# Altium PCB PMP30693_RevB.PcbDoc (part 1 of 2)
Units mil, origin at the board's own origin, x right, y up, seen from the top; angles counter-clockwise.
Board outline 2800 x 2253.94 mil, 2 copper layers (Top Layer, Bottom Layer), stack 62 mil thick; 97 components, 41 nets, 215 pads, 48 vias.
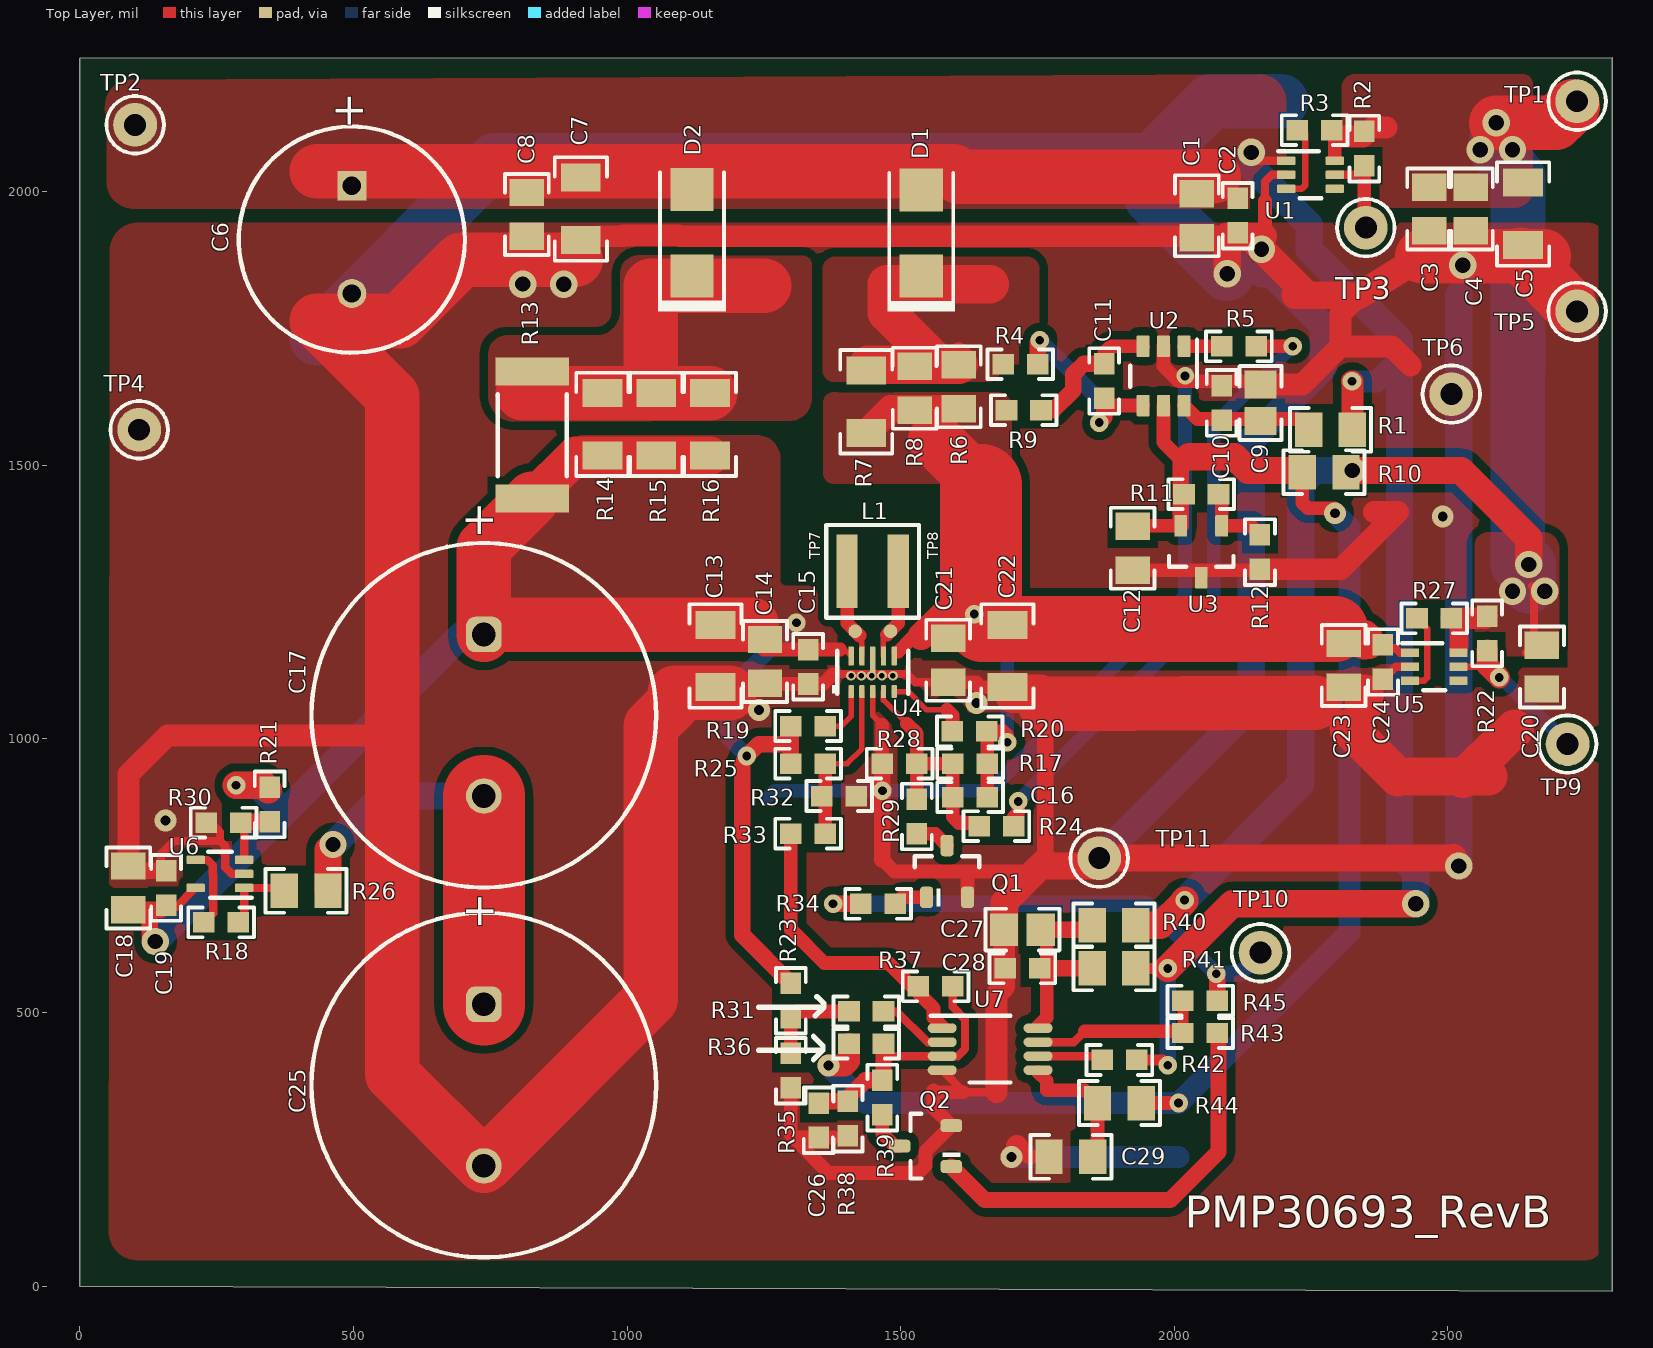
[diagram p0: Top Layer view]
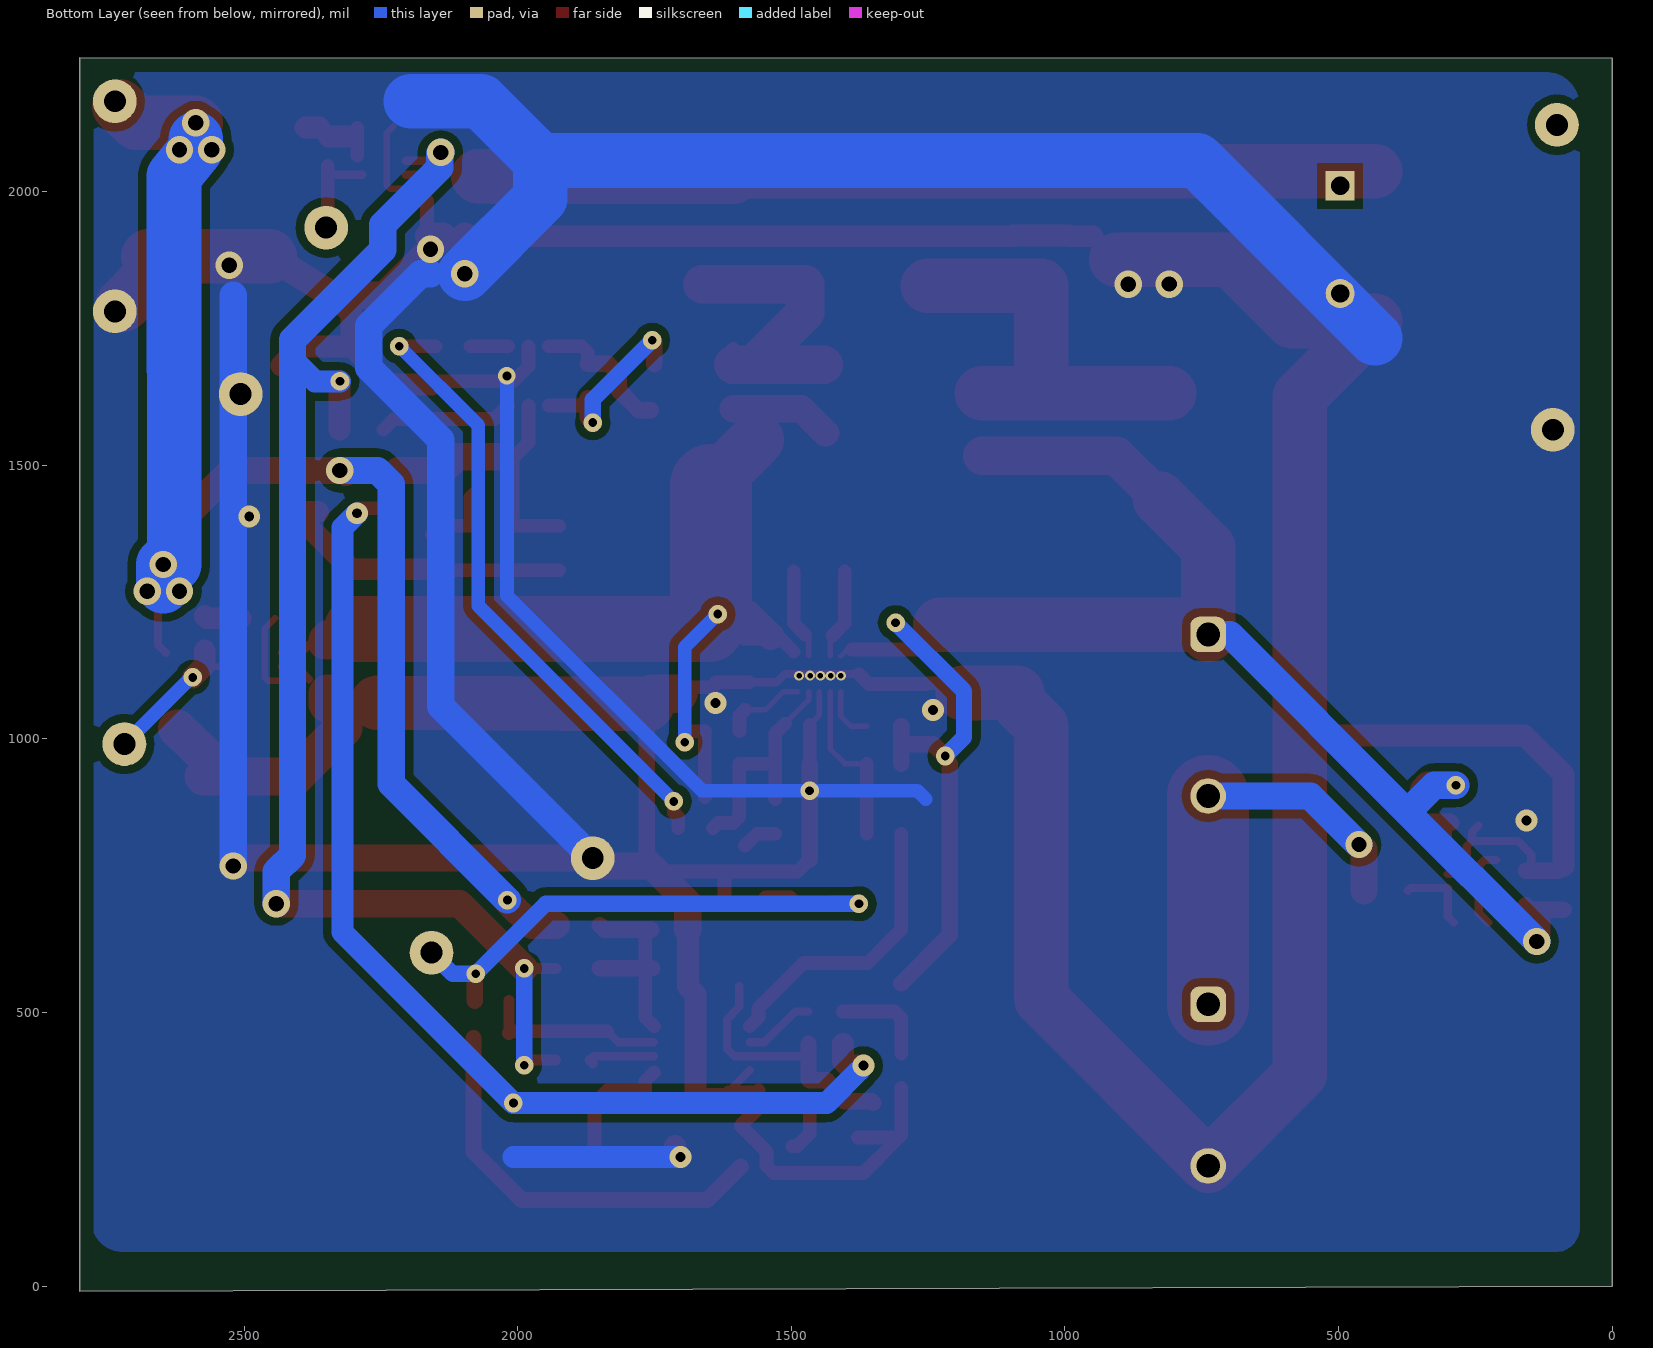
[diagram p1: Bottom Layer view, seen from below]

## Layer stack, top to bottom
Top Solder: solder mask 0.4, Solder Resist, Dk 3.5
Top Layer: signal copper 1.4
Dielectric1: core 59.2, FR-4, Dk 4.8
Bottom Layer: signal copper 1.4
Bottom Solder: solder mask 0.4, Solder Resist, Dk 3.5

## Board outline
0,0 0,2244.09 2800,2244.56 2800,-9.38

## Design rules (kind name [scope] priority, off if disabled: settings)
AcuteAngle [All] p1: minimum=4.50000000000000E+0001 checktracksonly=FALSE
AssemblyTestPointUsage [All] p1: valid=2
BoardOutlineClearance BoardOutlineClearance_MountingHoles [OnCopper and InComponentClass('Mounting Holes')] p1: gap=39.37 ignorepadtopadclearanceinfootprint=FALSE
BoardOutlineClearance BoardOutlineClearance_Poly [OnCopper and IsPoly] p2: gap=25 ignorepadtopadclearanceinfootprint=FALSE
BoardOutlineClearance [OnCopper and Not InComponentClass('Logo') and not InComponentClass('FiducialMark') and not InRegion(1000,500,4000,800) and not InPoly] p3: gap=15 ignorepadtopadclearanceinfootprint=FALSE
Clearance Clearance_Keepouts [((IsTrack Or IsArc) And Not InPoly) And IsFree and IsKeepOut vs ((IsTrack Or IsArc) And Not InPoly) And IsFree and IsKeepOut] p1: gap=0 ignorepadtopadclearanceinfootprint=FALSE
Clearance Clearance_Poly [InPolygon] p2: gap=15 ignorepadtopadclearanceinfootprint=TRUE
Clearance Clearance_FiducialMark [IsKeepOut and InComponentClass('FiducialMark') vs IsPad and InComponentClass('FiducialMark')] p3: gap=0 ignorepadtopadclearanceinfootprint=FALSE
Clearance [All] p4: gap=7.87 ignorepadtopadclearanceinfootprint=TRUE
ComponentClearance ComponentClearance_MountingHoles_FiducialMarks [InComponentClass('Mounting Holes') vs InComponentClass('FiducialMark')] p1: gap=50 collisioncheckmode=3 verticalgap=10 showdistances=FALSE
ComponentClearance ComponentClearance_Shunt [InComponentClass('Header') vs InComponentClass('Shunt')] p2: gap=0 collisioncheckmode=3 verticalgap=0 showdistances=FALSE
ComponentClearance ComponentClearance_Logo [InComponentClass('Logo')] p3: gap=50 collisioncheckmode=3 verticalgap=10 showdistances=FALSE
ComponentClearance ComponentClearance_ScrewToNut [(HasFootprint('NY PMS 440 0025 PH')) vs (HasFootprint('Keystone_1902C'))] p4: gap=5 collisioncheckmode=3 verticalgap=10 showdistances=FALSE
ComponentClearance ComponentClearance_MountingHoles [InComponentClass('Mounting Holes')] p5: gap=250 collisioncheckmode=3 verticalgap=100000 showdistances=FALSE
ComponentClearance ComponentClearance_SmallPassives [HasFootprint('0201*') or HasFootprint('0402*') or HasFootprint('0508') or HasFootprint('0603*') or HasFootprint('0612') or HasFootprint('0805*') or HasFootprint('0815*') or HasFootprint('0830*') or HasFootprint('1206*') or HasFootprint('1210*') or HasFootprint('1808*') or HasFootprint('1812*') or HasFootprint('1825*') or HasFootprint('2010*') or HasFootprint('2220*') or HasFootprint('2225*') or HasFootprint('2512*') or HasFootprint('2728*') or HasFootprint('3518*') vs HasFootprint('0201*') or HasFootprint('0402*') or HasFootprint('0508') or HasFootprint('0603*') or HasFootprint('0612') or HasFootprint('0805*') or HasFootprint('0815*') or HasFootprint('0830*') or HasFootprint('1206*') or HasFootprint('1210*') or HasFootprint('1808*') or HasFootprint('1812*') or HasFootprint('1825*') or HasFootprint('2010*') or HasFootprint('2220*') or HasFootprint('2225*') or HasFootprint('2512*') or HasFootprint('2728*') or HasFootprint('3518*')] p6: gap=14.96 collisioncheckmode=3 verticalgap=10 showdistances=FALSE
ComponentClearance ComponentClearance_THtoSMT [IsThruComponent vs IsSMTComponent] p7: gap=20 collisioncheckmode=3 verticalgap=20 showdistances=FALSE
ComponentClearance ComponentClearance_THtoTH [IsThruComponent vs IsThruComponent] p8: gap=30 collisioncheckmode=3 verticalgap=30 showdistances=FALSE
ComponentClearance [All] p9: gap=6 collisioncheckmode=3 verticalgap=6 showdistances=FALSE
DiffPairsRouting [All] p1: maxlimit=100 minlimit=10 mostfreqgap=10 toplayer_minwidth=15 toplayer_maxwidth=15 toplayer_prefwidth=15 bottomlayer_minwidth=15 bottomlayer_maxwidth=15 bottomlayer_prefwidth=15 maxuncoupledlength=1000
FabricationTestPointUsage TestPointUsage [All] p1: valid=2 allowmultiple=FALSE
FabricationTestpoint Testpoint [All] p1: side=3 testpointundercomponent=TRUE minsize=40 maxsize=100 preferedsize=60 minholesize=0 maxholesize=40 preferedholesize=32 testpointgrid=1 allowsidetop=TRUE allowsidebottom=TRUE usegrid=TRUE gridtolerance=0.01
FanoutControl Fanout_LCC [IsLCC] p1: bgadir=Out bgaviamode=Centered fanoutstyle=Auto fanoutdirection=Alternating viagrid=1 // Fanout_LCC (Default Rule)
FanoutControl Fanout_BGA [IsBGA] p2: bgadir=Out bgaviamode=Centered fanoutstyle=Auto fanoutdirection=Alternating viagrid=1 // Fanout_BGA (Default Rule)
FanoutControl Fanout_Default [All] p4: bgadir=Out bgaviamode=Centered fanoutstyle=Auto fanoutdirection=Alternating viagrid=1 // Fanout_Default (Default Rule)
FanoutControl Fanout_Small [(CompPinCount < 5)] p5: bgadir=Out bgaviamode=Centered fanoutstyle=Auto fanoutdirection=OutThenIn viagrid=1 // Fanout_Small (Default Rule)
Height [All] p1: minheight=0 maxheight=3000 prefheight=500
HoleSize [All] p1: absolutevalues=TRUE maxlimit=251 minlimit=7.87 maxpercent=80.000 minpercent=20.000
HoleToHoleClearance [All] p1: gap=7 allowstackedmicrovias=TRUE
MinimumAnnularRing MinimumAnnularRing_ThermalPadVias [IsVia and InAnyComponent] p1: minimumring=5.91
MinimumAnnularRing [All] p2: minimumring=4
MinimumSolderMaskSliver MinimumSolderMaskSliver_Logo [InComponentClass('Logo') vs InComponentClass('Logo')] p1: minsoldermaskwidth=0.7
MinimumSolderMaskSliver [All] p2: minsoldermaskwidth=1
PlaneConnect [All] p1: planeconnectstyle=Relief reliefexpansion=10 reliefentries=4 reliefconductorwidth=10 reliefairgap=10
PolygonConnect [All] p1: connectstyle=Direct reliefconductorwidth=10 reliefentries=4 polygonreliefangle="90 Angle" airgapwidth=10
RoutingVias ThermalPadVias [IsVia and InAnyComponent] p1: holewidth=7.87 width=19.68 viastyle="Through Hole" minholewidth=7.87 minwidth=19.68 maxholewidth=12.99 maxwidth=23.62
RoutingVias [All] p2: holewidth=16 width=34 viastyle="Through Hole" minholewidth=6 minwidth=15 maxholewidth=40 maxwidth=65
SilkToBoardRegionClearance [Not ((IsComment or IsDesignator) And (Hide <> 'False')) and not InRegion(1000,500,4000,800)] p1:
SilkToSilkClearance SilkToSilkClearance_Pb-FreeLogo [(HasFootprint('Pb-Free_Overlay_Medium') OR HasFootprint('Pb-Free_Overlay_Small')) vs (HasFootprint('Pb-Free_Overlay_Medium') OR HasFootprint('Pb-Free_Overlay_Small'))] p1 off: silktosilkclearance=0
SilkToSilkClearance [All] p2 off: silktosilkclearance=3.94
SilkToSolderMaskClearance SilkToComponentPadClearance [(IsPad or IsFill or IsRegion) and InAnycomponent] p1 off: minsilkscreentomaskgap=5 clearancetoexposedcopper=TRUE
SilkToSolderMaskClearance "Silk to Solder Mask Opening" [All] p2 off: minsilkscreentomaskgap=3.94 clearancetoexposedcopper=FALSE
SolderMaskExpansion [All] p1: expansion=1.97
UnRoutedNet [All] p1: checkbadconnections=TRUE
Width [All] p1: maxlimit=200 minlimit=6 preferedwidth=10 checkconnectedcopper=TRUE
12 further rules are at their usual default settings.

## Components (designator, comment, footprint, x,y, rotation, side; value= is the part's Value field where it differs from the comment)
C1 "GRM21BR71A105KA01L" 0805_HV 2041.14,1956.25 r270 top value=1uF
C2 "GRM188R71H104KA93D" 0603 2115.62,1956.25 r270 top value=0.1uF
C3 "GRM21BR71A105KA01L" 0805_HV 2465.62,1968.5 r270 top value=1uF
C4 "GRM21BR70J106KE76L" 0805_HV 2541.86,1968.5 r270 top value=10uF
C5 "DNP" 1206 2637.5,1959.38 r270 top
C6 "EKZM160ELL102MJ20S" Chemi-Con_1000x2000 496.88,1912.5 r270 top value=1000uF
C7 "DNP" 1206 915.35,1968.5 r270 top
C8 "GRM21BR70J106KE76L" 0805_HV 816.93,1958.66 r270 top value=10uF
C9 "DNP" 0805 2157.48,1614.17 r90 top
C10 "GRM188R71H104KA93D" 0603 2086.61,1614.17 r90 top value=0.1uF
C11 "C0603C334K4RACTU" 0603 1871.88,1654.13 r270 top value=0.33uF
C12 "C0805C155K8RACTU" 0805_HV 1923.86,1348.43 r270 top value=1.5uF
C13 "DNP" 1206 1161.42,1151.57 r270 top
C14 "GRM21BR70J106KE76L" 0805_HV 1251.97,1141.73 r270 top value=10uF
C15 "GRM188R71H104KA93D" 0603 1330.71,1131.89 r270 top value=0.1uF
C16 "Used in BOM report" 0603 1626.7,893.7 r180 top value=DNP
C17 "SCCU25B256SRB" SCC_1600x2650 738.19,1043.31 r270 top value=25000000uF
C18 "GRM21BR71A105KA01L" 0805_HV 88.58,727.72 r90 top value=1uF
C19 "GRM188R71H104KA93D" 0603 157.48,727.72 r90 top value=0.1uF
C20 "GRM21BR71A105KA01L" 0805_HV 2671.88,1131.25 r270 top value=1uF
C21 "CL21B226MQQNNNE" 0805_HV 1586.61,1143.7 r270 top value=22uF
C22 "Used in BOM report" 1206 1694.88,1151.57 r270 top value=DNP
C23 "GRM21BR71A105KA01L" 0805_HV 2309.38,1134.38 r270 top value=1uF
C24 "GRM188R71H104KA93D" 0603 2381.25,1140.62 r270 top value=0.1uF
C25 "SCCU25B256SRB" SCC_1600x2650 738.19,367.42 r270 top value=25000000uF
C26 "DNP" 0603 1350,303.12 r270 top
C27 "Used in BOM report" 0805 1722.44,651.57 r180 top value=DNP
C28 "GRM188R71H104KA93D" 0603 1722.44,580.71 r180 top value=0.1uF
C29 "C0805C105K8RACTU" 0805_HV 1811.02,236.22 r180 top value=1uF
D1 "MBRA210LT3G" SMA 1537.5,1924.75 r90 top value=10V
D2 "MBRA210LT3G" SMA 1118.75,1925 r90 top value=10V
L1 "XFL4015-471MEC" XFL4015 1448.82,1306.25 r0 top value=470nH
Q1 "MMBT2222A" SOT-23 1584.65,757.87 r90 top value="40 V"
Q2 "MMBT2222A" SOT-23 1545.28,255.91 r180 top value="40 V"
R1 "CRCW08050000Z0EA" 0805_HV 2285.43,1564.96 r0 top value=0
R2 "CRCW06030000Z0EA" 0603 2347.25,2078.81 r90 top value=0
R3 "CRCW06030000Z0EA" 0603 2256.25,2112.5 r180 top value=0
R4 "CRCW0603499RFKEA" 0603 1718.56,1684.72 r0 top value=499
R5 "CRCW06030000Z0EA" 0603 2118.11,1717.52 r180 top value=0
R6 "Used in BOM report" 0805_HV 1606.3,1643.7 r90 top value=DNP
R7 "ERJ-8BWFR068V" 1206 1437.01,1616.14 r90 top value=0.068
R8 "Used in BOM report" 0805_HV 1525.59,1641 r90 top value=DNP
R9 "CRCW0603499RFKEA" 0603 1724.84,1600.82 r0 top value=499
R10 "CRCW08052K00FKEA" 0805_HV 2273.62,1487.5 r180 top value=2.00k
R11 "CRCW0603100RFKEA" 0603 2049.21,1447.3 r180 top value=100
R12 "CRCW060312K4FKEA" 0603 2156.5,1341.54 r90 top value=12.4k
R13 "Used in BOM report" 2512 826.77,1555.12 r90 top value=DNP
R14 "CRCW120630R1FKEA" 1206 954.72,1574.8 r90 top value=30.1
R15 "CRCW120630R1FKEA" 1206 1053.15,1574.8 r90 top value=30.1
R16 "CRCW120630R1FKEA" 1206 1151.57,1574.8 r90 top value=30.1
R17 "CRCW0603392KFKEA" 0603 1626.7,954.72 r0 top value=392k
R18 "CRCW06030000Z0EA" 0603 257.87,664.72 r0 top value=0
R19 "CRCW06030000Z0EA" 0603 1330.71,1023.62 r0 top value=0
R20 "CRCW0603100KFKEA" 0603 1625.98,1013.78 r0 top value=100k
R21 "CRCW06031M00FKEA" 0603 346.88,880.3 r90 top value=1.00Meg
R22 "CRCW06030000Z0EA" 0603 2571.88,1192.91 r90 top value=0
R23 "CRCW0603301KFKEA" 0603 1299.21,521.65 r90 top value=301k
R24 "CRCW0603100KFKEA" 0603 1675,840.62 r0 top value=100k
R25 "DNP" 0603 1330.71,954.72 r0 top
R26 "CRCW08051K00FKEA" 0805_HV 413.39,722.44 r0 top value=1.00k
R27 "CRCW06030000Z0EA" 0603 2475,1220.47 r180 top value=0
R28 "CRCW060382K5FKEA" 0603 1498.03,954.72 r0 top value=82.5k
R29 "CRCW0603187KFKEA" 0603 1529.53,858.27 r90 top value=187k
R30 "CRCW06031M00FKEA" 0603 262.5,846.88 r0 top value=1.00Meg
R31 "CRCW06030000Z0EA" 0603 1437.01,501.97 r0 top value=0
R32 "DNP" 0603 1387.5,895.67 r0 top
R33 "CRCW060310K0FKEA" 0603 1330.71,826.77 r0 top value=10.0k
R34 "CRCW0603100KFKEA" 0603 1458.66,698.82 r180 top value=100k
R35 "CRCW060343K2FKEA" 0603 1299.21,393.7 r90 top value=43.2k
R36 "CRCW0603100KFKEA" 0603 1437.01,442.91 r0 top value=100k
R37 "CRCW06033M01FKEA" 0603 1563.78,548.06 r180 top value=3.01Meg
R38 "CRCW060390K9FKEA" 0603 1403.12,306.25 r90 top value=90.9k
R39 "CRCW06030000Z0EA" 0603 1466.54,344.49 r270 top value=0
R40 "CRCW08050000Z0EA" 0805_HV 1889.76,659.45 r180 top value=0
R41 "DNP" 0805_HV 1889.76,580.71 r180 top
R42 "CRCW060310K0FKEA" 0603 1899.61,413.39 r180 top value=10.0k
R43 "CRCW0603100KFKEA" 0603 2047.24,462.6 r0 top value=100k
R44 "CRCW0805100RJNEA" 0805_HV 1899.61,334.65 r180 top value=100
R45 "CRCW06030000Z0EA" 0603 2047.24,521.65 r0 top value=0
TP1 "5000" Keystone5000 2736.22,2165.35 r90 top
TP2 "5000" Keystone5000 100.88,2122.33 r90 top
TP3 "5000" Keystone5000 2350,1934.38 r90 top
TP4 "5001" Keystone5001 108.27,1564.96 r90 top
TP5 "5001" Keystone5001 2736.22,1781.5 r90 top
TP6 "5001" Keystone5001 2506.25,1630.14 r90 top
TP7 "TP-025-SMT" TP_25MIL-SMT 1416.82,1196.88 r90 top value=STD
TP8 "TP-025-SMT" TP_25MIL-SMT 1481.17,1196.97 r90 top value=STD
TP9 "5000" Keystone5000 2718.75,990.62 r90 top
TP10 "5000" Keystone5000 2157.48,609.38 r90 top
TP11 "5001" Keystone5001 1862.8,782.09 r90 top
U1 "LM66100DCKT" DCK0006A_N 2248.83,2031.23 r0 top
U2 "INA181A4IDBV" DBV0006A_N 1980.31,1663.39 r270 top
U3 "TLV431AIDBZR" DBZ0003A_N 2049.21,1342.16 r270 top
U4 "TPS63802DLAR" DLA0010A 1448.82,1122.05 r90 top
U5 "LM66100DCKT" DCK0006A_N 2475,1131.89 r0 top
U6 "TLV521DCKR" DCK0005A_N 255.91,753.31 r180 top
U7 "TLV522DGKR" DGK0008A_N 1663.39,433.07 r0 top

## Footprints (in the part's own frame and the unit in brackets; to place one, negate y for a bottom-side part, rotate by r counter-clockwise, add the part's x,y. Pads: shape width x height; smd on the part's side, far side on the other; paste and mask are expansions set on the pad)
0603 [mm] "0603 from SM-752 data"
  rect 1x0.95 smd: 1(-0.8,0) 2(0.8,0)
  silkscreen extent -1.52,-0.69 1.52,0.69, body extent -0.87,-0.47 0.87,0.47, height 1
0805 [mm] "0805 from SM-752 data"
  rect 1.3x1.5 smd: 1(-0.85,0) 2(0.85,0)
  silkscreen extent -1.72,-0.97 1.72,0.97, body extent -1.1,-0.72 1.1,0.72, height 1.45
0805_HV [mil] "0805 with 30mil clearance between pads"
  rect 50x63 smd: 1(-40,0) 2(40,0)
  silkscreen extent -74,-40 74,40, body extent -43,-29 43,29, height 57
1206 [mm] "1206 from SM-752 data"
  rect 1.3x1.85 smd: 1(-1.45,0) 2(1.45,0)
  silkscreen extent -2.4,-1.21 2.4,1.21, body extent -1.7,-0.9 1.7,0.9, height 1.35
2512 [mm] "Chip Resistor, Body 6.3x3.2mm, IPC Medium Density"
  rect 1.3x3.4 smd: 1(-2.95,0) 2(2.95,0)
  silkscreen extent -1.9,-1.6 1.9,1.6, body extent -3.22,-1.67 3.22,1.67, height 0.71
Chemi-Con_1000x2000 [mm] "TH, 2-Leads, Body 10x20mm, Pin Spacing 5mm"
  rect 1.35x1.35 hole 0.85: 1(-2.5,0)
  round 1.35 hole 0.85: 2(2.5,0)
  silkscreen extent -5.25,-5.25 5.25,5.25, body extent -5.25,-5.25 5.25,5.25, height 21.5
DBV0006A_N [mm] "SOT23, 6-Leads, Body 2.9x1.6mm, Pitch 0.95mm, Lead Span 2.8mm, IPC Medium Density"
  rrect17% 1x0.6 smd: 1(-1.375,0.95) 2(-1.375,0) 3(-1.375,-0.95) 4(1.375,-0.95) 5(1.375,0) 6(1.375,0.95)
  silkscreen extent -1.68,-1.55 0.5,1.55, body extent -1.42,-1.46 1.42,1.46, height 1.12
DBZ0003A_N [mm] "SOT23, 3-Leads, Body 2.9x1.3mm, Pitch 0.95mm, Lead Span 2.4mm, IPC Medium Density"
  rrect17% 1x0.6 smd: 1(-1.2,0.95) 2(-1.2,-0.95) 3(1.2,0)
  silkscreen extent 0.2,-1.5 0.7,1.5, body extent -1.26,-1.46 1.26,1.46, height 0.98
DCK0005A_N [mm] "SOT353, 5-Leads, Body 2x1.3mm, Pitch 0.65mm, Lead Span 2.1mm, IPC Medium Density"
  rrect25% 0.85x0.4 smd: 1(-1.125,0.65) 2(-1.125,0) 3(-1.125,-0.65) 4(1.125,-0.65) 5(1.125,0.65)
  silkscreen extent -1.48,-1.02 0.55,1.1, body extent -1.14,-1 1.14,1, height 0.95
DCK0006A_N [mm] "SOT23, 6-Leads, Body 2x1.3mm, Pitch 0.65mm, Lead Span 2.1mm, IPC Medium Density"
  rrect25% 0.85x0.4 smd: 1(-1.125,0.65) 2(-1.125,0) 3(-1.125,-0.65) 4(1.125,-0.65) 5(1.125,0) 6(1.125,0.65)
  silkscreen extent -1.5,-1.09 0.51,1.09, body extent -1.14,-1 1.14,1, height 0.95
DGK0008A_N [mm] "TSOP, 8-Leads, Body 3x3mm, Pitch 0.65mm, IPC Medium Density"
  oval 1.35x0.45 smd: 1(-2.225,0.975) 2(-2.225,0.325) 3(-2.225,-0.325) 4(-2.225,-0.975) 5(2.225,-0.975) 6(2.225,-0.325) 7(2.225,0.325) 8(2.225,0.975)
  silkscreen extent -2.75,-1.55 0.95,1.55, body extent -2.45,-1.5 2.45,1.5, height 0.96
DLA0010A [mm] "VQFN-HR-10"
  rrect40% 0.6x0.25 smd: 1(-0.9,1) 2(-0.9,0.5) 3(-0.9,0) 4(-0.9,-0.5) 5(-0.9,-1)
  rrect40% 0.9x0.25 smd: 6(0.75,-1) 7(0.75,-0.5) 9(0.75,0.5) 10(0.75,1)
  rrect40% 1.3x0.25 smd paste-1: 8(0.55,0)
  silkscreen extent -1,-1.65 1,1.9, body extent -1,-1.5 1,1.5, height 1
Keystone5000 [mil] "For Keystone 500x miniature loop terminals"
  round 80 hole 40: 1(0,0)
  silkscreen extent -52,-52 52,52, body extent -49,-49 49,49, height 182
Keystone5001 [mil] "For Keystone 500x miniature loop terminals"
  round 80 hole 40: 1(0,0)
  silkscreen extent -52,-52 52,52, body extent -49,-49 49,49, height 182
SCC_1600x2650 [mm] "TH, 2-Leads, Dia 16mm, Pin Spacing 7.5mm"
  rrect50% 1.65x1.65 hole 1.1: 1(-3.75,0)
  round 1.65 hole 1.1: 2(3.75,0)
  silkscreen extent -8,-8 8,8, body extent -8,-8 8.01,8, height 26.51
SMA [mm] "Molded Diode, 2-Leads, Body 4.3x2.6mm, IPC Medium Density, based on OnSemi component dimensions and land pattern"
  rect 2x2 smd: 1(-2,0) 2(2,0)
  silkscreen extent -3.66,-1.57 2.79,1.57, body extent -2.6,-1.3 2.6,1.3, height 2.42
SOT-23 [mm] "SOT23, 3-Leads, Body 2.9x1.3mm, Pitch 0.95mm, Lead Span 2.5mm, IPC Medium Density"
  rrect50% 1x0.6 smd: 1(-1.2,0.95) 2(-1.2,-0.95) 3(1.2,0)
  silkscreen extent -1.62,-1.5 0.7,1.5, body extent -1.16,-1.45 1.21,1.45, height 1
TP_25MIL-SMT [mil]
  round 25 smd mask-2.5: 1(0,0)
XFL4015 [mm] "SMD, 2-Leads, Body 4x4mm"
  rect 0.98x3.4 smd: 1(-1.185,0) 2(1.185,0)
  silkscreen extent -2.15,-2.15 2.15,2.15, body extent -2.15,-2.15 2.15,2.15, height 1.6

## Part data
C1 C3 C18 C20 C23: "CAP, CERM, 1 µF, 10 V,+/- 10%, X7R, 0805", Cap_Case=0805, Manufacturer=MuRata, Supplier Part Number 1=490-1695-1-ND, TempCo=X7R, Tolerance_%=10, Value1="0.007 ohm", Value2=10V, ValueDisplayed=1µF
C2 C10 C15 C19 C24 C28: "CAP, CERM, 0.1 µF, 50 V,+/- 10%, X7R, 0603", Cap_Case=0603, Manufacturer=MuRata, Supplier Part Number 1=490-1519-1-ND, TempCo=X7R, Tolerance_%=10, Value2=50V, ValueDisplayed=0.1µF
C4 C8 C14: "CAP, CERM, 10 µF, 6.3 V,+/- 10%, X7R, 0805", Cap_Case=0805, Manufacturer=MuRata, Supplier Part Number 1=490-3904-1-ND, TempCo=X7R, Tolerance_%=10, Value2=6.3V, ValueDisplayed=10µF
C5 C7 C9 C13 C26: library part Capacitor, "CAP, CERM, xxxF, xxV, [TempCo], xx%, [PackageReference]", Alternate Manufacturer=-, Manufacturer="Used in BOM report"
C6: library part EKZE160ELL102MJ20S, "CAP, AL, 1000 µF, 16 V, +/- 20%, TH", Cap_Case=10x20, Manufacturer=Chemi-Con, Supplier Part Number 1=565-1664-ND, Tolerance_%=20, Value2=16V, ValueDisplayed=1000µF
C11: "CAP, CERM, 0.33 µF, 16 V,+/- 10%, X7R, 0603", Cap_Case=0603, Manufacturer=Kemet, Supplier Part Number 1=399-4916-1-ND, TempCo=X7R, Tolerance_%=10, Value2=16V, ValueDisplayed=0.33µF
C12: "CAP, CERM, 1.5 µF, 10 V,+/- 10%, X7R, 0805", Cap_Case=0805, Manufacturer=Kemet, Supplier Part Number 1=399-4931-1-ND, TempCo=X7R, Tolerance_%=10, Value1="0.009 ohm", Value2=10V, ValueDisplayed=1.5µF
C16 C22 C27: library part Capacitor, "CAP, CERM, xxxF, xxV, [TempCo], xx%, [PackageReference]", Alternate Manufacturer=-
C17 C25: library part CMP-0860272-1, "CAP, Electric Double Layer, 25000000 µF, 2.7 V,+30/--10%, 0.027 ohm, TH", Cap_Case=16x25mm, Manufacturer=AVX, Tolerance_%=30%, Value1="0.027 ohm", Value2=2.7V, ValueDisplayed=25F
C21: "CAP, CERM, 22 µF, 6.3 V,+/- 20%, X7R, 0805", Cap_Case=0805, Manufacturer="Samsung Electro-Mechanics", TempCo=X7R, Tolerance_%=20, Value2=6.3V, ValueDisplayed=22µF
C29: "CAP, CERM, 1 µF, 10 V,+/- 10%, X7R, 0805", Cap_Case=0805, Manufacturer=Kemet, Supplier Part Number 1=399-1172-1-ND, TempCo=X7R, Tolerance_%=10, Value1="0.015 ohm", Value2=10V, ValueDisplayed=1µF
D1 D2: "Diode, Schottky, 10 V, 2 A, SMA", Manufacturer="ON Semiconductor", Supplier Part Number 1=MBRA210LT3GOSCT-ND, Value1=2A, Value2=0.35V
L1: library part CMP-0061147-1, "Inductor, Shielded, Composite, 470 nH, 3.5 A, 0.0076 ohm, SMD", Manufacturer=Coilcraft, Supplier Part Number 1=994-XFL4015-471MEC, Value1="0.0076 ohm", Value2=3.5A, ValueDisplayed=470nH
Q1 Q2: library part CMP-0000385-1, "Transistor, NPN, 40 V, 0.15 A, SOT-23", Manufacturer="Fairchild Semiconductor", Supplier Part Number 1=MMBT2222AFSCT-ND, Value1="0.15 A", Value2=300
R1 R40: "RES, 0, 5%, 0.125 W, 0805", Manufacturer=Vishay-Dale, Power_W=0.125, Supplier Part Number 1=541-0.0ACT-ND, TempCo="200 ppm/C", Tolerance_%=5, Value1=5%, Value2=0.125W, Value_Code=0000, ValueDisplayed=0
R2 R3 R5 R18 R19 R22 R27 R31 R39 R45: "RES, 0, 5%, 0.1 W, 0603", Manufacturer=Vishay-Dale, Power_W=0.1, Supplier Part Number 1=541-0.0GCT-ND, TempCo="200 ppm/C", Tolerance_%=5, Value1=5%, Value2=0.1W, Value_Code=0000, ValueDisplayed=0
R4 R9: "RES, 499, 1%, 0.1 W, 0603", Manufacturer=Vishay-Dale, Power_W=0.1, Supplier Part Number 1=541-499HCT-ND, TempCo="100 ppm/C", Tolerance_%=1, Value1=1%, Value2=0.1W, Value_Code=499R, ValueDisplayed=499
R6 R8 R13: library part Resistor, "RES, xxx ohm, x%, xW, [PackageReference]", Alternate Manufacturer=-
R7: library part ERJ-8BWFR075V, "RES, 0.068, 1%, 0.5 W, 1206", Manufacturer=Panasonic, Power_W=0.5, Supplier Part Number 1=1577544, TempCo="150 ppm/C", Tolerance_%=1, Value1=1%, Value2=0.5W, Value_Code=R068, ValueDisplayed=0.068
R10: "RES, 2.00 k, 1%, 0.125 W, 0805", Manufacturer=Vishay-Dale, Power_W=0.125, Supplier Part Number 1=541-2.00KCCT-ND, TempCo="100 ppm/C", Tolerance_%=1, Value1=1%, Value2=0.125W, Value_Code=2k00, ValueDisplayed=2.00k
R11: "RES, 100, 1%, 0.1 W, 0603", Manufacturer=Vishay-Dale, Power_W=0.1, Supplier Part Number 1=541-100HCT-ND, TempCo="100 ppm/C", Tolerance_%=1, Value1=1%, Value2=0.1W, Value_Code=100R, ValueDisplayed=100
R12: "RES, 12.4 k, 1%, 0.1 W, 0603", Manufacturer=Vishay-Dale, Power_W=0.1, Supplier Part Number 1=541-12.4KHCT-ND, TempCo="100 ppm/C", Tolerance_%=1, Value1=1%, Value2=0.1W, Value_Code=12k4, ValueDisplayed=12.4k
R14 R15 R16: "RES, 30.1, 1%, 0.25 W, 1206", Manufacturer=Vishay-Dale, Power_W=0.25, Supplier Part Number 1=541-30.1FCT-ND, TempCo="100 ppm/C", Tolerance_%=1, Value1=1%, Value2=0.25W, Value_Code=30R1, ValueDisplayed=30.1
R17: "RES, 392 k, 1%, 0.1 W, 0603", Manufacturer=Vishay-Dale, Power_W=0.1, Supplier Part Number 1=541-392KHCT-ND, TempCo="100 ppm/C", Tolerance_%=1, Value1=1%, Value2=0.1W, Value_Code=392k
R20 R24 R34 R36 R43: "RES, 100 k, 1%, 0.1 W, 0603", Manufacturer=Vishay-Dale, Power_W=0.1, Supplier Part Number 1=541-100KHCT-ND, TempCo="100 ppm/C", Tolerance_%=1, Value1=1%, Value2=0.1W, Value_Code=100k
R21 R30: "RES, 1.00 M, 1%, 0.1 W, 0603", Manufacturer=Vishay-Dale, Power_W=0.1, Supplier Part Number 1=541-1.00MHCT-ND, TempCo="100 ppm/C", Tolerance_%=1, Value1=1%, Value2=0.1W, Value_Code=1M00, ValueDisplayed=1.00M
R23: "RES, 301 k, 1%, 0.1 W, 0603", Manufacturer=Vishay-Dale, Power_W=0.1, Supplier Part Number 1=541-301KHCT-ND, TempCo="100 ppm/C", Tolerance_%=1, Value1=1%, Value2=0.1W, Value_Code=301k
R25 R32 R41: library part Resistor, "RES, xxx ohm, x%, xW, [PackageReference]", Alternate Manufacturer=-, Manufacturer="Used in BOM report"
R26: "RES, 1.00 k, 1%, 0.125 W, 0805", Manufacturer=Vishay-Dale, Power_W=0.125, Supplier Part Number 1=541-1.00KCCT-ND, TempCo="100 ppm/C", Tolerance_%=1, Value1=1%, Value2=0.125W, Value_Code=1k00, ValueDisplayed=1.00k
R28: "RES, 82.5 k, 1%, 0.1 W, 0603", Manufacturer=Vishay-Dale, Power_W=0.1, Supplier Part Number 1=541-82.5KHCT-ND, TempCo="100 ppm/C", Tolerance_%=1, Value1=1%, Value2=0.1W, Value_Code=82k5, ValueDisplayed=82.5k
R29: "RES, 187 k, 1%, 0.1 W, 0603", Manufacturer=Vishay-Dale, Power_W=0.1, Supplier Part Number 1=541-187KHCT-ND, TempCo="100 ppm/C", Tolerance_%=1, Value1=1%, Value2=0.1W, Value_Code=187k
R33 R42: "RES, 10.0 k, 1%, 0.1 W, 0603", Manufacturer=Vishay-Dale, Power_W=0.1, Supplier Part Number 1=541-10.0KHCT-ND, TempCo="100 ppm/C", Tolerance_%=1, Value1=1%, Value2=0.1W, Value_Code=10k0, ValueDisplayed=10.0k
R35: "RES, 43.2 k, 1%, 0.1 W, 0603", Manufacturer=Vishay-Dale, Power_W=0.1, Supplier Part Number 1=541-43.2KHCT-ND, TempCo="100 ppm/C", Tolerance_%=1, Value1=1%, Value2=0.1W, Value_Code=43k2, ValueDisplayed=43.2k
R37: "RES, 3.01 M, 1%, 0.1 W, 0603", Manufacturer=Vishay-Dale, Power_W=0.1, Supplier Part Number 1=541-3.01MHCT-ND, TempCo="100 ppm/C", Tolerance_%=1, Value1=1%, Value2=0.1W, Value_Code=3M01, ValueDisplayed=3.01M
R38: "RES, 90.9 k, 1%, 0.1 W, 0603", Manufacturer=Vishay-Dale, Power_W=0.1, Supplier Part Number 1=541-90.9KHCT-ND, TempCo="100 ppm/C", Tolerance_%=1, Value1=1%, Value2=0.1W, Value_Code=90k9, ValueDisplayed=90.9k
R44: "RES, 100, 5%, 0.125 W, 0805", Manufacturer=Vishay-Dale, Power_W=0.125, Supplier Part Number 1=541-100ACT-ND, TempCo="200 ppm/C", Tolerance_%=5, Value1=5%, Value2=0.125W, Value_Code=100R, ValueDisplayed=100
TP1 TP2 TP3 TP9 TP10: "Test Point, Miniature, Red, TH", Color=Red, Manufacturer=Keystone, Supplier Part Number 1=36-5000-ND
TP4 TP5 TP6 TP11: "Test Point, Miniature, Black, TH", Color=Black, Manufacturer=Keystone, Supplier Part Number 1=36-5001-ND
TP7 TP8: "Test Point, O.025\"", Manufacturer=STD
U1 U5: library part CMP-0085652-1, "+/-6V, Low IQ Ideal Diode with Input Polarity Protection, DCK0006A (SOT-SC70-6)", Alternate Manufacturer="Texas Instruments", Alternate PartNumber=LM66100DCKR
U2: library part CMP-0013228-2, "Bidirectional, Low- and High-Side Measurement, Multichannel, Voltage Output, Current-Sense Amplifier, DBV0006A (SOT-6)", Alternate Manufacturer="Texas Instruments"
U3: library part CMP-0033044-1, "Low Voltage Adjustable Precision Shunt Regulator, 39 ppm / degC, 15 mA, -40 to 85 degC, 3-pin SOT-23 (DBZ), Green (RoHS & no Sb/Br)", Manufacturer="Texas Instruments", Rating=Catalog, Temp Coeff(Max)(ppm/ degree C)=129, Temp Coeff(Typ)(ppm/ degree C)=39
U4: library part CMP-0076712-5, "High Current, High Efficiency Single Inductor Buck-Boost Converter, DLA0010A (VSON-HR-10)", Alternate Manufacturer="Texas Instruments", Alternate PartNumber=TPS63802DLAT, Operating Temperature Range="-40 to 125 C"
U6: library part CMP-0084062-1, "350-nA Nanopower, Single, RRIO, CMOS Input, Operational Amplifier for Cost-Sensitive Systems, DCK0005A (SOT-SC70-5)", Alternate Manufacturer="Texas Instruments", Alternate PartNumber=TLV521DCKT, Operating Temperature Range="-40 to 125 C", Rating=Catalog
U7: library part CMP-0860538-1, "500-nA Nanopower, Dual, RRIO, CMOS-Input Operational Amplifier for Cost-Sensitive Systems, DGK0008A (VSSOP-8)", Alternate Manufacturer="Texas Instruments", Alternate PartNumber=TLV522DGKT, Operating Temperature Range="-40 to 125 C", Rating=Catalog

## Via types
v1: diameter 34, hole 16, Top Layer to Bottom Layer, 18 vias
v2: diameter 50, hole 28, Top Layer to Bottom Layer, 17 vias
v3: diameter 40, hole 18, Top Layer to Bottom Layer, 7 vias
v4: diameter 18, hole 10, Top Layer to Bottom Layer, 5 vias
v5: diameter 32, hole 16, Top Layer to Bottom Layer, 1 vias

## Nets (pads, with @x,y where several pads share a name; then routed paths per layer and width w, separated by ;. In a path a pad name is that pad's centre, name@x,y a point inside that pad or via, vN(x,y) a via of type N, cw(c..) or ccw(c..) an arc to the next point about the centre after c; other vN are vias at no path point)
FB: R5.1 R24.2 | length 1159
  Top Layer w25: R24.2@1706.69,836.61 1706.69,857.28 1714.57,865.16 v1(1714.57,885.83) ; R5.1@2149.61,1717.52 v1(2216.54,1717.52)
  Bottom Layer w25: v1(1714.57,885.83) 2071.88,1243.13 2071.88,1572.86 v1(2216.54,1717.52)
